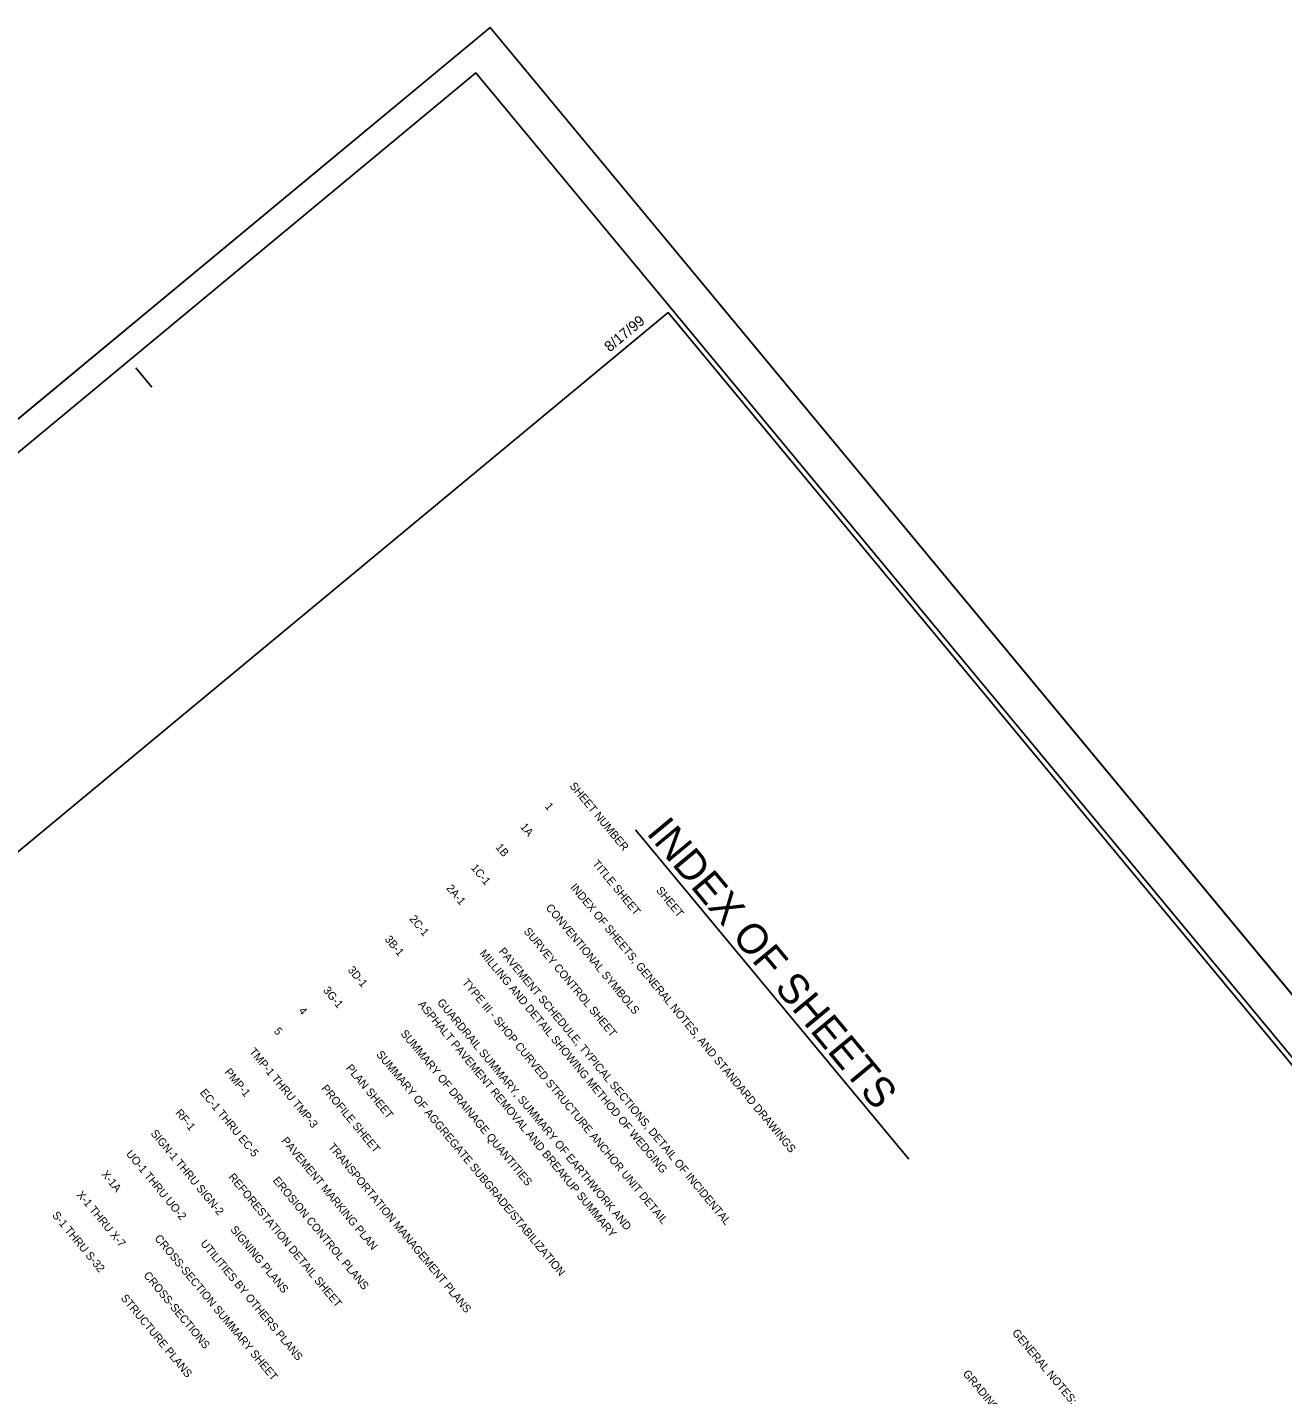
# Model space of a CAD drawing. Extents: x 2054826 to 2060231, y 685508 to 690809.
# Drawn here: x 2055437 to 2056065, y 686820 to 687503 of the extents above; entities that cross this region are included whole.
import ezdxf

# ---------------------------------------------------------------- set-up
doc = ezdxf.new("R2010")
doc.units = 0
for name, color, linetype in [('Prop DSN Text', 7, 'Continuous'), ('Sheet Cutting Line CELL', 7, 'Continuous'), ('Sheet Plan CELL', 7, 'Continuous'), ('Sheet Plot Border Inside CELL', 7, 'Continuous'), ('Sheet Plot Border Outside CELL', 7, 'Continuous')]:
    doc.layers.add(name, color=color, linetype=linetype)

msp = doc.modelspace()

# ---------------------------------------------------------------- linework, layer by layer
at = {"layer": 'Prop DSN Text'}
msp.add_line((2055741.47, 687102.15), (2055877.96, 686937.55), dxfattribs=at)
at = {"layer": 'Sheet Cutting Line CELL'}
for p, q in [((2055668.74, 687503.24), (2054825.85, 686804.27)), ((2056743.36, 686207.34), (2055668.74, 687503.24))]:
    msp.add_line(p, q, dxfattribs=at)
at = {"layer": 'Sheet Plan CELL'}
for p, q in [((2055757.7, 687360.71), (2055757.7, 687360.71)), ((2055491.64, 687332.99), (2055499.62, 687323.37))]:
    msp.add_line(p, q, dxfattribs=at)
msp.add_lwpolyline([(2056715.19, 686206.06), (2055757.7, 687360.71), (2054949.45, 686690.47), (2055906.94, 685535.82)], close=True, dxfattribs=at)
at = {"layer": 'Sheet Plot Border Inside CELL'}
msp.add_lwpolyline([(2054849.54, 686807.03), (2055912.99, 685524.6), (2056725.1, 686198.04), (2055661.64, 687480.47)], close=True, dxfattribs=at)
at = {"layer": 'Sheet Plot Border Outside CELL'}
msp.add_lwpolyline([(2054825.85, 686804.27), (2055900.47, 685508.37), (2056743.36, 686207.34), (2055668.74, 687503.24)], close=True, dxfattribs=at)

# ---------------------------------------------------------------- texts
at = {"layer": 'Prop DSN Text'}
for s, height, p in [('SHEET NUMBER                 SHEET   ', 4, (2055708.19, 687123.96)), ('1                       TITLE SHEET', 4, (2055695.87, 687113.75)), ('1A                      INDEX OF SHEETS, GENERAL NOTES, AND STANDARD DRAWINGS', 4, (2055683.56, 687103.53)), ('INDEX OF SHEETS', 15, (2055746.47, 687100.4)), ('1B                      CONVENTIONAL SYMBOLS ', 4, (2055671.24, 687093.32)), ('1C-1                    SURVEY CONTROL SHEET', 4, (2055658.92, 687083.11)), ('2A-1                    PAVEMENT SCHEDULE, TYPICAL SECTIONS, DETAIL OF INCIDENTAL', 4, (2055646.61, 687072.89)), ('2C-1                    TYPE III - SHOP CURVED STRUCTURE ANCHOR UNIT DETAIL', 4, (2055628.13, 687057.57)), ('3B-1                    GUARDRAIL SUMMARY, SUMMARY OF EARTHWORK AND', 4, (2055615.82, 687047.36)), ('                        MILLING AND DETAIL SHOWING METHOD OF WEDGING', 4, (2055640.45, 687067.79)), ('3D-1                    SUMMARY OF DRAINAGE QUANTITIES', 4, (2055597.34, 687032.04)), ('3G-1                    SUMMARY OF AGGREGATE SUBGRADE/STABILIZATION', 4, (2055585.03, 687021.83)), ('                        ASPHALT PAVEMENT REMOVAL AND BREAKUP SUMMARY', 4, (2055609.66, 687042.25)), ('4                       PLAN SHEET', 4, (2055572.71, 687011.61)), ('5                       PROFILE SHEET', 4, (2055560.39, 687001.4)), ('TMP-1 THRU TMP-3        TRANSPORTATION MANAGEMENT PLANS', 4, (2055548.08, 686991.19)), ('PMP-1                   PAVEMENT MARKING PLAN', 4, (2055535.76, 686980.97)), ('EC-1 THRU EC-5          EROSION CONTROL PLANS', 4, (2055523.44, 686970.76)), ('RF-1                    REFORESTATION DETAIL SHEET', 4, (2055511.13, 686960.55)), ('SIGN-1 THRU SIGN-2      SIGNING PLANS', 4, (2055498.81, 686950.33)), ('UO-1 THRU UO-2          UTILITIES BY OTHERS PLANS', 4, (2055486.5, 686940.12)), ('X-1A                    CROSS-SECTION SUMMARY SHEET', 4, (2055474.18, 686929.91)), ('X-1 THRU X-7            CROSS-SECTIONS', 4, (2055461.86, 686919.7)), ('S-1 THRU S-32           STRUCTURE PLANS', 4, (2055449.55, 686909.48)), ('GENERAL NOTES:                         2012 SPECIFICATIONS', 4, (2055929.43, 686850.68)), ('GRADING AND SURFACING OR RESURFACING AND WIDENING:  ', 4, (2055904.8, 686830.25))]:
    msp.add_text(s, height=height, rotation=309.66721, dxfattribs=at).set_placement(p)
at = {"layer": 'Sheet Plan CELL'}
msp.add_text('8/17/99', height=5.25, rotation=39.66721, dxfattribs=at).set_placement((2055728.53, 687340.74))

doc.saveas('drawing.dxf')
